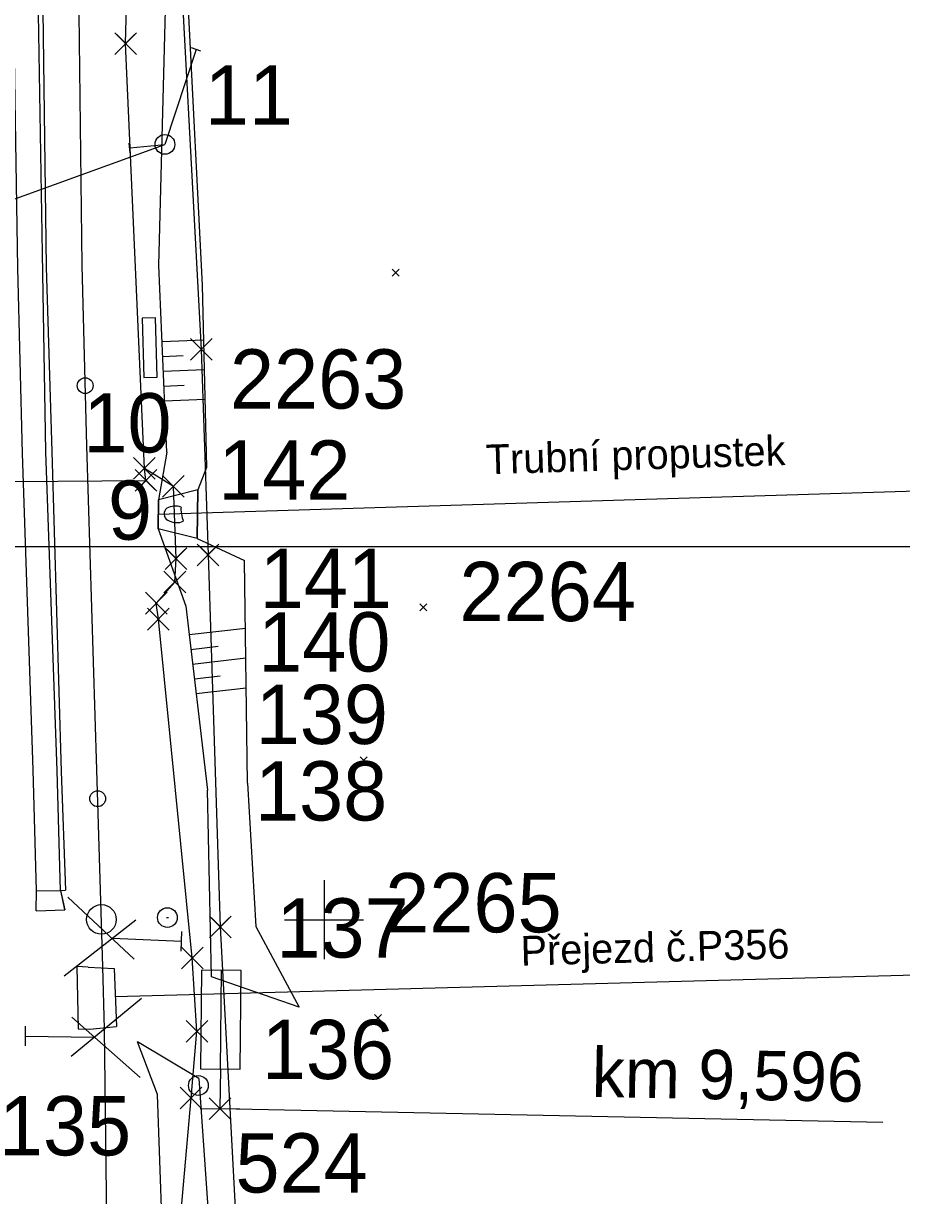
# Model space of a CAD drawing. Extents: x -866402 to -860377, y -1041908 to -1038598.
# Drawn here: x -862515.2 to -862470.8, y -1039514 to -1039454.6 of the extents above; entities that cross this region are included whole.
import ezdxf

# ---------------------------------------------------------------- set-up
doc = ezdxf.new("R2010")
doc.units = 0
for name, color, linetype in [('PS 01 prvky', 7, 'Continuous'), ('PS 02 trasa', 7, 'Continuous'), ('SO 01 trasa', 7, 'Continuous'), ('SZDC', 7, 'Continuous'), ('Vrstva 1', 7, 'Continuous'), ('Vrstva 14', 7, 'Continuous'), ('Vrstva 19', 7, 'Continuous'), ('Vrstva 23', 7, 'Continuous'), ('Vrstva 29', 7, 'Continuous'), ('Vrstva 36', 7, 'Continuous'), ('Vrstva 4', 7, 'Continuous'), ('Vrstva 48', 7, 'Continuous'), ('Vrstva 49', 7, 'Continuous'), ('Vrstva 5', 7, 'Continuous'), ('Vrstva 60', 7, 'Continuous'), ('Vrstva 7', 7, 'Continuous')]:
    doc.layers.add(name, color=color, linetype=linetype)

msp = doc.modelspace()

# ---------------------------------------------------------------- linework, layer by layer
at = {"layer": 'PS 01 prvky'}
for p, q in [((-862506.196, -1039502.55), (-862506.247, -1039507.55)), ((-862504.196, -1039502.571), (-862506.196, -1039502.55)), ((-862504.248, -1039507.571), (-862504.196, -1039502.571)), ((-862506.247, -1039507.55), (-862504.248, -1039507.571)), ((-862505.247, -1039507.56), (-862505.268, -1039509.56)), ((-862506.268, -1039509.55), (-862504.268, -1039509.571)), ((-862505.268, -1039509.56), (-862471.724, -1039510.247))]:
    msp.add_line(p, q, dxfattribs=at)
msp.add_lwpolyline([(-862505.247, -1039507.56), (-862505.196, -1039502.561)], dxfattribs=at)
at = {"layer": 'PS 02 trasa'}
msp.add_lwpolyline([(-862545.675, -1039649.8), (-862530.757, -1039623.443), (-862522.932, -1039604.729), (-862515.46, -1039580.555), (-862510.685, -1039555.744), (-862508.634, -1039530.584), (-862506.732, -1039509.025), (-862506.431, -1039505.647), (-862506.665, -1039501.934), (-862508.381, -1039484.78), (-862508.488, -1039483.971), (-862507.551, -1039482.903), (-862507.488, -1039481.712), (-862507.623, -1039478.057), (-862509.092, -1039477.147), (-862510.044, -1039455.637), (-862509.722, -1039443.838), (-862509.261, -1039426.925), (-862506.583, -1039405.984), (-862500.946, -1039382.238), (-862490.795, -1039355.075), (-862481.411, -1039336.582)], dxfattribs=at)
at = {"layer": 'SO 01 trasa'}
msp.add_line((-862428.976, -1039481.123), (-862522.864, -1039481.123), dxfattribs=at)
for points in [[(-862509.092, -1039477.147), (-862510.044, -1039455.637), (-862509.722, -1039443.838)], [(-862523.418, -1039477.868), (-862522.407, -1039477.868), (-862509.015, -1039477.758), (-862509.092, -1039477.147)]]:
    msp.add_lwpolyline(points, dxfattribs=at)
at = {"layer": 'SZDC'}
msp.add_lwpolyline([(-862296.71, -1039229.87), (-862316.65, -1039230.71), (-862348.72, -1039238.93), (-862380.51, -1039253.6), (-862410.85, -1039277.18), (-862440.53, -1039308.72), (-862448.041, -1039316.665), (-862455.094, -1039324.01), (-862466.781, -1039329.472), (-862479.414, -1039335.377), (-862482.88, -1039349.12), (-862498.59, -1039394.48), (-862504.52, -1039414.78), (-862507.77, -1039442.09), (-862507.542, -1039446.341), (-862506.21, -1039471.12), (-862505.869, -1039481.526), (-862505.252, -1039500.361), (-862503.67, -1039530.107), (-862504.256, -1039560.514), (-862512.94, -1039597.44), (-862522.209, -1039619.87), (-862533.818, -1039639.468), (-862574.405, -1039691.562)], dxfattribs=at)
at = {"layer": 'Vrstva 1'}
msp.add_line((-862511.504, -1039492.405), (-862512.008, -1039476.004), dxfattribs=at)
for points in [[(-862512.008, -1039476.004), (-862512.24, -1039466.872), (-862512.447, -1039449.843), (-862512.083, -1039433.477), (-862510.815, -1039417.563), (-862508.369, -1039401.798), (-862504.899, -1039386.684), (-862500.227, -1039371.447), (-862494.61, -1039356.985), (-862487.828, -1039342.57)], [(-862635.332, -1039727.958), (-862628.97, -1039724.203), (-862616.242, -1039716.357), (-862603.065, -1039707.367), (-862590.534, -1039697.467), (-862579.031, -1039687.004), (-862568.051, -1039675.519), (-862557.584, -1039662.818), (-862548.498, -1039650.05), (-862539.563, -1039635.323), (-862531.648, -1039619.628), (-862525.205, -1039604.056), (-862519.84, -1039587.785), (-862515.903, -1039571.791), (-862513.102, -1039555.188), (-862511.487, -1039538.764), (-862510.91, -1039522.217), (-862511.107, -1039505.516), (-862511.189, -1039502.39), (-862511.504, -1039492.405)]]:
    msp.add_lwpolyline(points, dxfattribs=at)
for centre in [(-862512.085, -1039472.959), (-862511.458, -1039493.873)]:
    msp.add_circle(centre, 0.4, dxfattribs=at)
at = {"layer": 'Vrstva 14'}
for p, q in [((-862513.337, -1039498.511), (-862513.112, -1039499.506)), ((-862513.112, -1039499.506), (-862513.314, -1039498.516)), ((-862514.561, -1039499.544), (-862513.112, -1039499.506))]:
    msp.add_line(p, q, dxfattribs=at)
for points in [[(-862514.561, -1039499.544), (-862514.554, -1039498.529), (-862514.716, -1039492.412), (-862515.255, -1039476.387), (-862515.499, -1039467.006), (-862515.758, -1039449.95), (-862515.668, -1039438.97), (-862515.562, -1039437.9)], [(-862513.337, -1039498.511), (-862513.51, -1039492.456), (-862514.077, -1039476.314), (-862514.247, -1039466.275), (-862514.515, -1039450.046), (-862514.361, -1039439.946), (-862514.131, -1039437.986)], [(-862514.131, -1039437.986), (-862514.402, -1039439.011), (-862514.256, -1039438.985), (-862514.278, -1039450.05), (-862514.061, -1039466.962), (-862513.769, -1039476.294), (-862513.311, -1039492.497), (-862513.092, -1039498.508)], [(-862514.554, -1039498.529), (-862513.314, -1039498.516), (-862513.092, -1039498.508)]]:
    msp.add_lwpolyline(points, dxfattribs=at)
at = {"layer": 'Vrstva 19'}
for p, q in [((-862508.386, -1039479.465), (-862451.927, -1039477.729)), ((-862508.4, -1039480.216), (-862508.373, -1039478.739)), ((-862506.378, -1039478.236), (-862508.373, -1039478.739)), ((-862506.427, -1039480.694), (-862506.378, -1039478.236)), ((-862506.427, -1039480.694), (-862508.4, -1039480.216))]:
    msp.add_line(p, q, dxfattribs=at)
for centre, major_axis, ratio, start_param, end_param in [((-862507.814, -1039479.454), (0.022, -0.33), 0.844729, 3.594117, 5.84317), ((-862507.569, -1039480.454), (0.126, 1.395), 0.788056, 6.091749, 6.75366), ((-862507.117, -1039479.472), (0.08, -0.451), 0.211616, 3.719805, 5.531751), ((-862507.699, -1039478.804), (0.585, -1.004), 0.730262, 5.379853, 6.271032)]:
    msp.add_ellipse(centre, major_axis=major_axis, ratio=ratio, start_param=start_param, end_param=end_param, dxfattribs=at)
at = {"layer": 'Vrstva 23'}
msp.add_lwpolyline([(-862508.523, -1039469.527), (-862509.199, -1039469.544), (-862509.123, -1039472.539), (-862508.447, -1039472.522)], close=True, dxfattribs=at)
at = {"layer": 'Vrstva 29'}
msp.add_line((-862534.25, -1039470.251), (-862508.049, -1039460.744), dxfattribs=at)
at = {"layer": 'Vrstva 36'}
for p, q in [((-862506.479, -1039455.938), (-862508.049, -1039460.744)), ((-862506.239, -1039456.017), (-862506.714, -1039455.861)), ((-862509.807, -1039461.176), (-862509.857, -1039460.678)), ((-862509.832, -1039460.924), (-862508.049, -1039460.744))]:
    msp.add_line(p, q, dxfattribs=at)
for centre in [(-862508.049, -1039460.744), (-862506.357, -1039508.392)]:
    msp.add_circle(centre, 0.5, dxfattribs=at)
at = {"layer": 'Vrstva 4'}
for p, q in [((-862509.604, -1039501.996), (-862512.972, -1039498.849)), ((-862513.143, -1039502.845), (-862509.518, -1039499.998)), ((-862507.234, -1039501.598), (-862507.192, -1039500.598)), ((-862507.213, -1039501.098), (-862510.71, -1039500.948)), ((-862511.944, -1039502.408), (-862512.512, -1039502.36)), ((-862512.512, -1039502.36), (-862512.435, -1039505.531)), ((-862511.944, -1039502.408), (-862510.616, -1039502.465)), ((-862510.616, -1039502.465), (-862510.505, -1039505.408)), ((-862510.562, -1039503.891), (-862451.171, -1039502.282)), ((-862509.245, -1039503.981), (-862512.791, -1039506.926)), ((-862515.117, -1039505.39), (-862515.133, -1039506.39)), ((-862512.76, -1039504.927), (-862509.307, -1039507.981)), ((-862511.857, -1039505.54), (-862510.505, -1039505.408)), ((-862515.125, -1039505.89), (-862511.625, -1039505.944)), ((-862512.435, -1039505.531), (-862511.857, -1039505.54))]:
    msp.add_line(p, q, dxfattribs=at)
at = {"layer": 'Vrstva 48'}
for p, q in [((-862508.196, -1039470.731), (-862506.105, -1039470.642)), ((-862508.164, -1039471.48), (-862507.125, -1039471.436)), ((-862508.132, -1039472.23), (-862506.067, -1039472.142)), ((-862508.1, -1039472.979), (-862507.074, -1039472.935)), ((-862508.068, -1039473.728), (-862506.029, -1039473.642)), ((-862506.823, -1039485.566), (-862503.975, -1039485.234)), ((-862506.736, -1039486.311), (-862505.351, -1039486.15)), ((-862506.649, -1039487.056), (-862503.956, -1039486.742)), ((-862506.563, -1039487.801), (-862505.254, -1039487.649)), ((-862506.476, -1039488.546), (-862503.936, -1039488.25))]:
    msp.add_line(p, q, dxfattribs=at)
at = {"layer": 'Vrstva 49'}
for p, q in [((-862496.55, -1039467.062), (-862496.196, -1039467.416)), ((-862496.55, -1039467.416), (-862496.196, -1039467.062)), ((-862505.942, -1039477.1), (-862506.378, -1039478.236)), ((-862506.378, -1039478.236), (-862506.427, -1039480.694)), ((-862506.427, -1039480.694), (-862504.02, -1039481.803)), ((-862503.873, -1039493.09), (-862504.02, -1039481.803)), ((-862495.158, -1039484.002), (-862494.804, -1039484.356)), ((-862495.158, -1039484.356), (-862494.804, -1039484.002)), ((-862506.992, -1039484.116), (-862505.905, -1039493.447)), ((-862498.17, -1039491.745), (-862497.816, -1039492.099)), ((-862498.17, -1039492.099), (-862497.816, -1039491.745)), ((-862505.696, -1039502.892), (-862505.905, -1039493.447)), ((-862501.254, -1039504.428), (-862505.696, -1039502.892)), ((-862497.451, -1039504.796), (-862497.097, -1039505.15)), ((-862497.451, -1039505.15), (-862497.097, -1039504.796)), ((-862506.342, -1039508.043), (-862509.436, -1039506.185)), ((-862506.342, -1039508.043), (-862505.429, -1039520.967))]:
    msp.add_line(p, q, dxfattribs=at)
for points in [[(-862506.893, -1039453.565), (-862506.175, -1039467.87), (-862505.942, -1039477.1)], [(-862507.958, -1039476.321), (-862508.36, -1039466.879), (-862508.023, -1039453.925)], [(-862507.958, -1039476.321), (-862508.373, -1039478.739), (-862508.4, -1039480.216), (-862506.992, -1039484.116)], [(-862503.873, -1039493.09), (-862503.448, -1039500.345), (-862501.254, -1039504.428)], [(-862507.96, -1039522.207), (-862508.426, -1039508.843), (-862509.436, -1039506.185)]]:
    msp.add_lwpolyline(points, dxfattribs=at)
at = {"layer": 'Vrstva 5'}
for p, q in [((-862500, -1039498), (-862500, -1039502)), ((-862502, -1039500), (-862498, -1039500))]:
    msp.add_line(p, q, dxfattribs=at)
at = {"layer": 'Vrstva 60'}
for p, q in [((-862509.594, -1039456.087), (-862510.594, -1039455.087)), ((-862509.594, -1039455.187), (-862510.594, -1039456.187)), ((-862510.494, -1039456.087), (-862509.494, -1039455.087)), ((-862510.494, -1039455.187), (-862509.494, -1039456.187)), ((-862510.044, -1039455.637), (-862510.044, -1039455.637)), ((-862505.76, -1039471.57), (-862506.76, -1039470.57)), ((-862505.76, -1039470.67), (-862506.76, -1039471.67)), ((-862506.66, -1039471.57), (-862505.66, -1039470.57)), ((-862506.66, -1039470.67), (-862505.66, -1039471.67)), ((-862506.21, -1039471.12), (-862506.21, -1039471.12)), ((-862508.642, -1039477.597), (-862509.642, -1039476.597)), ((-862508.642, -1039476.697), (-862509.642, -1039477.697)), ((-862509.542, -1039477.597), (-862508.542, -1039476.597)), ((-862509.542, -1039476.697), (-862508.542, -1039477.697)), ((-862508.565, -1039478.208), (-862509.565, -1039477.208)), ((-862508.565, -1039477.308), (-862509.565, -1039478.308)), ((-862509.465, -1039478.208), (-862508.465, -1039477.208)), ((-862509.465, -1039477.308), (-862508.465, -1039478.308)), ((-862509.092, -1039477.147), (-862509.092, -1039477.147)), ((-862507.173, -1039478.507), (-862508.173, -1039477.507)), ((-862508.073, -1039478.507), (-862507.073, -1039477.507)), ((-862509.015, -1039477.758), (-862509.015, -1039477.758)), ((-862507.173, -1039477.607), (-862508.173, -1039478.607)), ((-862508.073, -1039477.607), (-862507.073, -1039478.607)), ((-862507.623, -1039478.057), (-862507.623, -1039478.057)), ((-862505.419, -1039481.976), (-862506.419, -1039480.976)), ((-862505.419, -1039481.076), (-862506.419, -1039482.076)), ((-862506.319, -1039481.976), (-862505.319, -1039480.976)), ((-862506.319, -1039481.076), (-862505.319, -1039482.076)), ((-862507.038, -1039482.162), (-862508.038, -1039481.162)), ((-862507.038, -1039481.262), (-862508.038, -1039482.262)), ((-862507.938, -1039482.162), (-862506.938, -1039481.162)), ((-862507.938, -1039481.262), (-862506.938, -1039482.262)), ((-862507.488, -1039481.712), (-862507.488, -1039481.712)), ((-862505.869, -1039481.526), (-862505.869, -1039481.526)), ((-862507.101, -1039483.353), (-862508.101, -1039482.353)), ((-862507.101, -1039482.453), (-862508.101, -1039483.453)), ((-862508.001, -1039483.353), (-862507.001, -1039482.353)), ((-862508.001, -1039482.453), (-862507.001, -1039483.453)), ((-862507.551, -1039482.903), (-862507.551, -1039482.903)), ((-862508.038, -1039484.421), (-862509.038, -1039483.421)), ((-862508.938, -1039484.421), (-862507.938, -1039483.421)), ((-862508.038, -1039483.521), (-862509.038, -1039484.521)), ((-862508.938, -1039483.521), (-862507.938, -1039484.521)), ((-862508.488, -1039483.971), (-862508.488, -1039483.971)), ((-862507.931, -1039485.23), (-862508.931, -1039484.23)), ((-862507.931, -1039484.33), (-862508.931, -1039485.33)), ((-862508.831, -1039485.23), (-862507.831, -1039484.23)), ((-862508.831, -1039484.33), (-862507.831, -1039485.33)), ((-862508.381, -1039484.78), (-862508.381, -1039484.78)), ((-862504.802, -1039500.811), (-862505.802, -1039499.811)), ((-862504.802, -1039499.911), (-862505.802, -1039500.911)), ((-862505.702, -1039500.811), (-862504.702, -1039499.811)), ((-862505.702, -1039499.911), (-862504.702, -1039500.911)), ((-862505.252, -1039500.361), (-862505.252, -1039500.361)), ((-862506.215, -1039502.384), (-862507.215, -1039501.384)), ((-862506.215, -1039501.484), (-862507.215, -1039502.484)), ((-862507.115, -1039502.384), (-862506.115, -1039501.384)), ((-862507.115, -1039501.484), (-862506.115, -1039502.484)), ((-862506.665, -1039501.934), (-862506.665, -1039501.934)), ((-862505.981, -1039506.097), (-862506.981, -1039505.097)), ((-862505.981, -1039505.197), (-862506.981, -1039506.197)), ((-862506.881, -1039506.097), (-862505.881, -1039505.097)), ((-862506.881, -1039505.197), (-862505.881, -1039506.197)), ((-862506.431, -1039505.647), (-862506.431, -1039505.647)), ((-862506.282, -1039509.475), (-862507.282, -1039508.475)), ((-862506.282, -1039508.575), (-862507.282, -1039509.575)), ((-862507.182, -1039509.475), (-862506.182, -1039508.475)), ((-862507.182, -1039508.575), (-862506.182, -1039509.575)), ((-862506.732, -1039509.025), (-862506.732, -1039509.025)), ((-862504.818, -1039510.01), (-862505.818, -1039509.01)), ((-862505.718, -1039510.01), (-862504.718, -1039509.01)), ((-862504.818, -1039509.11), (-862505.818, -1039510.11)), ((-862505.718, -1039509.11), (-862504.718, -1039510.11)), ((-862505.268, -1039509.56), (-862505.268, -1039509.56))]:
    msp.add_line(p, q, dxfattribs=at)
at = {"layer": 'Vrstva 7'}
msp.add_line((-862507.979, -1039499.889), (-862507.879, -1039499.889), dxfattribs=at)
for centre, radius in [((-862511.265, -1039499.986), 0.75), ((-862507.929, -1039499.889), 0.5)]:
    msp.add_circle(centre, radius, dxfattribs=at)

# ---------------------------------------------------------------- texts
at = {"layer": 'PS 01 prvky'}
msp.add_text('km 9,596', height=2.5, rotation=358.91237, dxfattribs=at).set_placement((-862486.464, -1039508.967))
at = {"layer": 'Vrstva 19'}
msp.add_text('Trubní propustek', height=1.5, rotation=1.76105, dxfattribs=at).set_placement((-862491.788, -1039477.446))
at = {"layer": 'Vrstva 4'}
msp.add_text('Přejezd č.P356', height=1.5, rotation=1.55218, dxfattribs=at).set_placement((-862490.031, -1039502.325))
at = {"layer": 'Vrstva 60'}
for s, p in [('11', (-862506.031, -1039459.743)), ('2263', (-862504.76, -1039474.12)), ('10', (-862512.178, -1039476.339)), ('142', (-862505.355, -1039478.729)), ('9', (-862510.934, -1039480.758)), ('141', (-862503.256, -1039484.217)), ('2264', (-862493.143, -1039484.88)), ('140', (-862503.334, -1039487.431)), ('139', (-862503.457, -1039491.103)), ('138', (-862503.495, -1039494.975)), ('2265', (-862496.9, -1039500.638)), ('137', (-862502.412, -1039501.915)), ('136', (-862503.149, -1039508.065)), ('135', (-862516.453, -1039511.93)), ('524', (-862504.483, -1039513.811))]:
    msp.add_text(s, height=3, dxfattribs=at).set_placement(p)

doc.saveas('drawing.dxf')
